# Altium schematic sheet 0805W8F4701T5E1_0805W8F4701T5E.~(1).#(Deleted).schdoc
size 127 x 99 mm
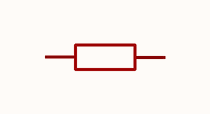
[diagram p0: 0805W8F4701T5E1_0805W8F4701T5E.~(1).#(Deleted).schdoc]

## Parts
R?  4.7kΩ  [R0805]  (value not drawn)

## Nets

Not connected (* = marked no-connect by the designer): R? 1 2

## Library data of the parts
R? = 0805W8F4701T5E: Manufacturer: UNI-ROYAL(厚声); Add into BOM: yes; Tolerance: ±1%; Power(Watts): 125mW; Overload Voltage (Max): 150V; Temperature Coefficient: ±100ppm/℃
